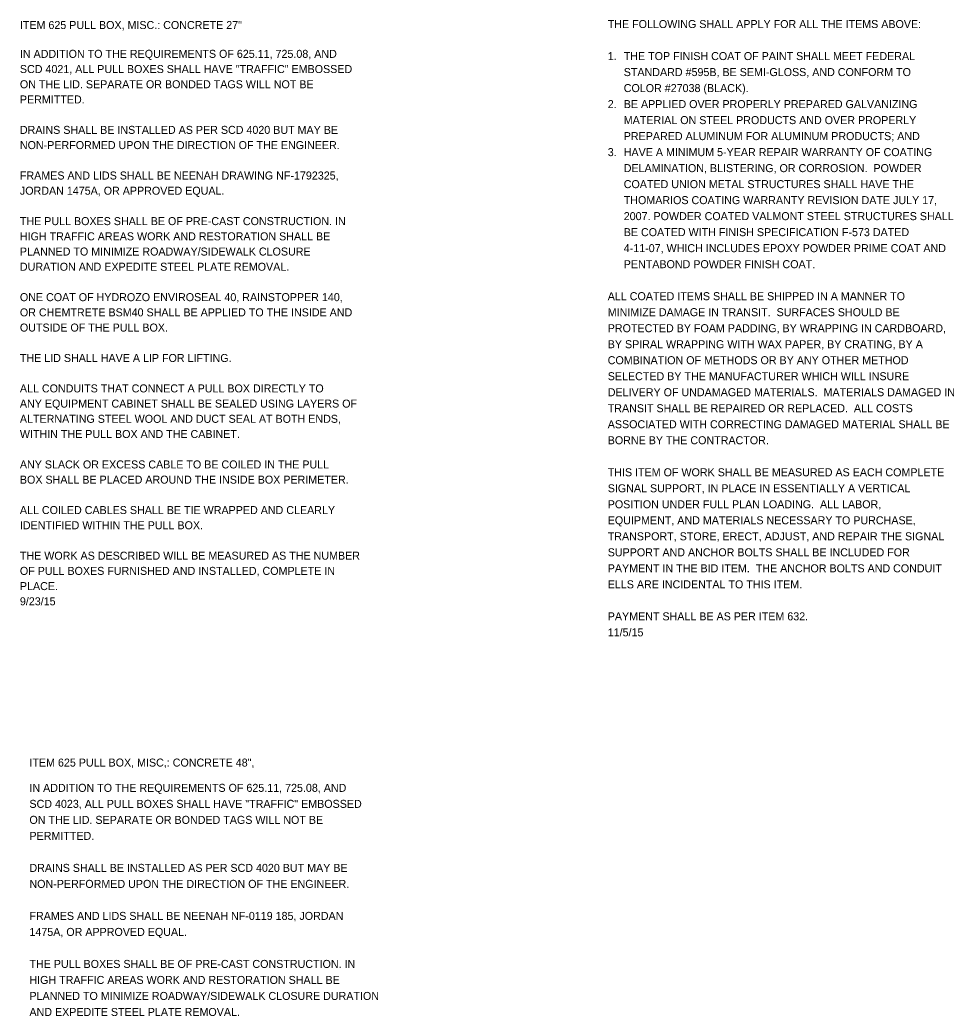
# Model space of a CAD drawing. Extents: x -27 to 74, y -37 to 38.
# Drawn here: x -27.37 to -11.02, y -7.59 to 9.84 of the extents above; entities that cross this region are included whole.
import ezdxf

# ---------------------------------------------------------------- set-up
doc = ezdxf.new("R2010")
doc.units = 0
doc.layers.add('SH_Data', color=7, linetype='Continuous')
doc.layers.add('SH_Text', color=7, linetype='Continuous')

msp = doc.modelspace()

# ---------------------------------------------------------------- texts
at = {"layer": 'SH_Data'}
for s, p in [('THE FOLLOWING SHALL APPLY FOR ALL THE ITEMS ABOVE:', (-17.081, 9.694)), ('1.', (-17.081, 9.134)), ('THE TOP FINISH COAT OF PAINT SHALL MEET FEDERAL ', (-16.801, 9.134)), ('STANDARD #595B, BE SEMI-GLOSS, AND CONFORM TO ', (-16.801, 8.854)), ('COLOR #27038 (BLACK).', (-16.801, 8.574)), ('2.', (-17.081, 8.294)), ('BE APPLIED OVER PROPERLY PREPARED GALVANIZING ', (-16.801, 8.294)), ('MATERIAL ON STEEL PRODUCTS AND OVER PROPERLY ', (-16.801, 8.014)), ('PREPARED ALUMINUM FOR ALUMINUM PRODUCTS; AND', (-16.801, 7.734)), ('3.', (-17.081, 7.454)), ('HAVE A MINIMUM 5-YEAR REPAIR WARRANTY OF COATING ', (-16.801, 7.454)), ('DELAMINATION, BLISTERING, OR CORROSION.  POWDER ', (-16.801, 7.174)), ('COATED UNION METAL STRUCTURES SHALL HAVE THE ', (-16.801, 6.894)), ('THOMARIOS COATING WARRANTY REVISION DATE JULY 17, ', (-16.801, 6.614)), ('2007. POWDER COATED VALMONT STEEL STRUCTURES SHALL ', (-16.801, 6.334)), ('BE COATED WITH FINISH SPECIFICATION F-573 DATED ', (-16.801, 6.054)), ('4-11-07, WHICH INCLUDES EPOXY POWDER PRIME COAT AND ', (-16.801, 5.774)), ('PENTABOND POWDER FINISH COAT.', (-16.801, 5.494)), ('ALL COATED ITEMS SHALL BE SHIPPED IN A MANNER TO ', (-17.081, 4.934)), ('MINIMIZE DAMAGE IN TRANSIT.  SURFACES SHOULD BE ', (-17.081, 4.654)), ('PROTECTED BY FOAM PADDING, BY WRAPPING IN CARDBOARD, ', (-17.081, 4.374)), ('BY SPIRAL WRAPPING WITH WAX PAPER, BY CRATING, BY A ', (-17.081, 4.094)), ('COMBINATION OF METHODS OR BY ANY OTHER METHOD ', (-17.081, 3.814)), ('SELECTED BY THE MANUFACTURER WHICH WILL INSURE ', (-17.081, 3.534)), ('DELIVERY OF UNDAMAGED MATERIALS.  MATERIALS DAMAGED IN ', (-17.081, 3.254)), ('TRANSIT SHALL BE REPAIRED OR REPLACED.  ALL COSTS ', (-17.081, 2.974)), ('ASSOCIATED WITH CORRECTING DAMAGED MATERIAL SHALL BE ', (-17.081, 2.694)), ('BORNE BY THE CONTRACTOR.', (-17.081, 2.414)), ('THIS ITEM OF WORK SHALL BE MEASURED AS EACH COMPLETE ', (-17.081, 1.854)), ('SIGNAL SUPPORT, IN PLACE IN ESSENTIALLY A VERTICAL ', (-17.081, 1.574)), ('POSITION UNDER FULL PLAN LOADING.  ALL LABOR, ', (-17.081, 1.294)), ('EQUIPMENT, AND MATERIALS NECESSARY TO PURCHASE, ', (-17.081, 1.014)), ('TRANSPORT, STORE, ERECT, ADJUST, AND REPAIR THE SIGNAL ', (-17.081, 0.734)), ('SUPPORT AND ANCHOR BOLTS SHALL BE INCLUDED FOR ', (-17.081, 0.454)), ('PAYMENT IN THE BID ITEM.  THE ANCHOR BOLTS AND CONDUIT ', (-17.081, 0.174)), ('ELLS ARE INCIDENTAL TO THIS ITEM.', (-17.081, -0.106)), ('PAYMENT SHALL BE AS PER ITEM 632. ', (-17.081, -0.666)), ('11/5/15', (-17.081, -0.946)), ('ITEM 625 PULL BOX, MISC,: CONCRETE 48",', (-27.199, -3.224)), ('IN ADDITION TO THE REQUIREMENTS OF 625.11, 725.08, AND ', (-27.199, -3.666)), ('SCD 4023, ALL PULL BOXES SHALL HAVE "TRAFFIC" EMBOSSED ', (-27.199, -3.946)), ('ON THE LID. SEPARATE OR BONDED TAGS WILL NOT BE ', (-27.199, -4.226)), ('PERMITTED. ', (-27.199, -4.506)), ('DRAINS SHALL BE INSTALLED AS PER SCD 4020 BUT MAY BE ', (-27.199, -5.066)), ('NON-PERFORMED UPON THE DIRECTION OF THE ENGINEER. ', (-27.199, -5.346)), ('FRAMES AND LIDS SHALL BE NEENAH NF-0119 185, JORDAN ', (-27.199, -5.906)), ('1475A, OR APPROVED EQUAL.', (-27.199, -6.186)), ('THE PULL BOXES SHALL BE OF PRE-CAST CONSTRUCTION. IN ', (-27.199, -6.746)), ('HIGH TRAFFIC AREAS WORK AND RESTORATION SHALL BE ', (-27.199, -7.026)), ('PLANNED TO MINIMIZE ROADWAY/SIDEWALK CLOSURE DURATION ', (-27.199, -7.306)), ('AND EXPEDITE STEEL PLATE REMOVAL.', (-27.199, -7.586))]:
    msp.add_text(s, height=0.14, dxfattribs=at).set_placement(p)
at = {"layer": 'SH_Text'}
for s, p in [('ITEM 625 PULL BOX, MISC.: CONCRETE 27"', (-27.366, 9.677)), ('IN ADDITION TO THE REQUIREMENTS OF 625.11, 725.08, AND ', (-27.366, 9.173)), ('SCD 4021, ALL PULL BOXES SHALL HAVE "TRAFFIC" EMBOSSED ', (-27.366, 8.907)), ('ON THE LID. SEPARATE OR BONDED TAGS WILL NOT BE ', (-27.366, 8.641)), ('PERMITTED. ', (-27.366, 8.375)), ('DRAINS SHALL BE INSTALLED AS PER SCD 4020 BUT MAY BE ', (-27.366, 7.843)), ('NON-PERFORMED UPON THE DIRECTION OF THE ENGINEER. ', (-27.366, 7.577)), ('FRAMES AND LIDS SHALL BE NEENAH DRAWING NF-1792325, ', (-27.366, 7.045)), ('JORDAN 1475A, OR APPROVED EQUAL.', (-27.366, 6.779)), ('THE PULL BOXES SHALL BE OF PRE-CAST CONSTRUCTION. IN ', (-27.366, 6.247)), ('HIGH TRAFFIC AREAS WORK AND RESTORATION SHALL BE ', (-27.366, 5.981)), ('PLANNED TO MINIMIZE ROADWAY/SIDEWALK CLOSURE ', (-27.366, 5.715)), ('DURATION AND EXPEDITE STEEL PLATE REMOVAL.', (-27.366, 5.449)), ('ONE COAT OF HYDROZO ENVIROSEAL 40, RAINSTOPPER 140, ', (-27.366, 4.917)), ('OR CHEMTRETE BSM40 SHALL BE APPLIED TO THE INSIDE AND ', (-27.366, 4.651)), ('OUTSIDE OF THE PULL BOX.', (-27.366, 4.385)), ('THE LID SHALL HAVE A LIP FOR LIFTING.', (-27.366, 3.853)), ('ALL CONDUITS THAT CONNECT A PULL BOX DIRECTLY TO ', (-27.366, 3.321)), ('ANY EQUIPMENT CABINET SHALL BE SEALED USING LAYERS OF ', (-27.366, 3.055)), ('ALTERNATING STEEL WOOL AND DUCT SEAL AT BOTH ENDS, ', (-27.366, 2.789)), ('WITHIN THE PULL BOX AND THE CABINET.', (-27.366, 2.523)), ('ANY SLACK OR EXCESS CABLE TO BE COILED IN THE PULL ', (-27.366, 1.991)), ('BOX SHALL BE PLACED AROUND THE INSIDE BOX PERIMETER.  ', (-27.366, 1.725)), ('ALL COILED CABLES SHALL BE TIE WRAPPED AND CLEARLY ', (-27.366, 1.193)), ('IDENTIFIED WITHIN THE PULL BOX.', (-27.366, 0.927)), ('THE WORK AS DESCRIBED WILL BE MEASURED AS THE NUMBER ', (-27.366, 0.395)), ('OF PULL BOXES FURNISHED AND INSTALLED, COMPLETE IN ', (-27.366, 0.129)), ('PLACE.', (-27.366, -0.137)), ('9/23/15', (-27.366, -0.403))]:
    msp.add_text(s, height=0.14, dxfattribs=at).set_placement(p)

doc.saveas('drawing.dxf')
